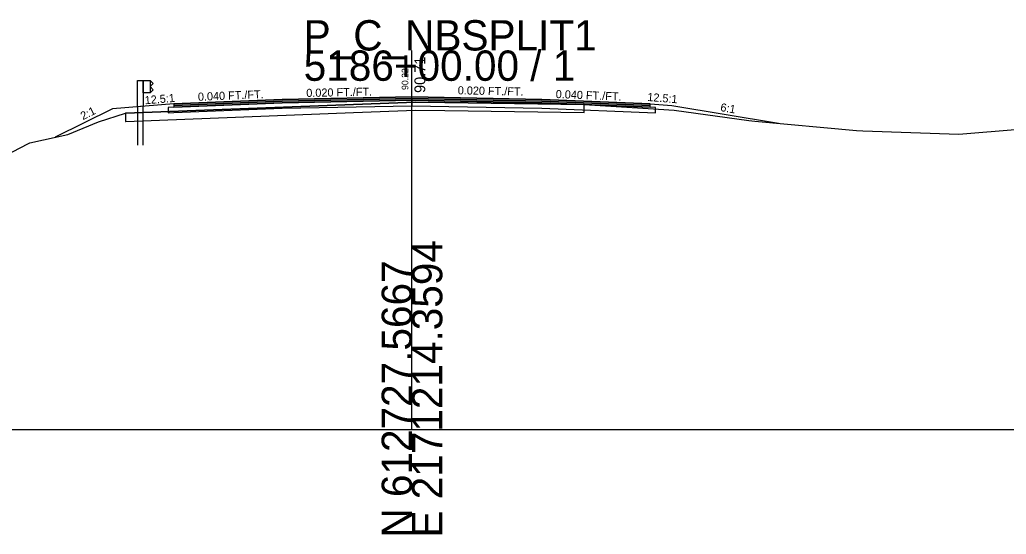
# Model space of a CAD drawing. Extents: x -26 to 1303, y -3010 to 12038.
# Drawn here: x 113.8 to 204.9, y 6490.3 to 6537.8 of the extents above; entities that cross this region are included whole.
import ezdxf

# ---------------------------------------------------------------- set-up
doc = ezdxf.new("R2010")
doc.units = 0
for name, color, linetype in [('RD_GPK_XS_Cell', 7, 'Continuous'), ('RD_PD_Final_TrvlWay', 7, 'Continuous'), ('RD_XS_Base', 7, 'Continuous'), ('RD_XS_ExGround', 7, 'Continuous'), ('RD_XS_ExPaveRet', 7, 'Continuous'), ('RD_XS_GR', 7, 'Continuous'), ('RD_XS_Greenside', 7, 'Continuous'), ('RD_XS_Pave', 7, 'Continuous'), ('RD_XS_PaveOvlay_CP', 7, 'Continuous'), ('RD_XS_TieSlope', 7, 'Continuous'), ('RD_XS_TX_Elev_EX', 7, 'Continuous'), ('RD_XS_TX_Elev_PR', 7, 'Continuous'), ('RD_XS_TX_ShdSlope', 7, 'Continuous'), ('RD_XS_TX_Slope', 7, 'Continuous')]:
    doc.layers.add(name, color=color, linetype=linetype)

msp = doc.modelspace()

# ---------------------------------------------------------------- linework, layer by layer
at = {"layer": 'RD_GPK_XS_Cell'}
for p, q in [((150, 6500), (150, 6535)), ((0, 6500), (150, 6500)), ((150, 6500), (300, 6500))]:
    msp.add_line(p, q, dxfattribs=at)
at = {"layer": 'RD_PD_Final_TrvlWay'}
for p, q in [((125.167, 6529.847), (124.667, 6529.807)), ((124.667, 6529.807), (124.667, 6526.242)), ((125.167, 6526.242), (125.167, 6529.847))]:
    msp.add_line(p, q, dxfattribs=at)
at = {"layer": 'RD_XS_Base'}
for p, q in [((138, 6530.156), (128, 6529.756)), ((150, 6530.396), (138, 6530.156)), ((138, 6530.156), (138, 6530.156)), ((150, 6530.396), (150, 6530.555)), ((150, 6530.555), (150, 6530.555)), ((150, 6530.555), (150, 6530.555)), ((150, 6530.555), (150, 6529.896)), ((150, 6529.896), (150, 6530.396)), ((150, 6530.396), (150, 6530.396)), ((150, 6530.396), (150, 6530.396)), ((150, 6530.396), (150, 6530.396)), ((162, 6530.156), (150, 6530.396)), ((172, 6529.756), (162, 6530.156)), ((164, 6530.076), (164, 6530.076)), ((128, 6529.756), (127.5, 6529.736)), ((127.5, 6529.736), (127.5, 6529.736)), ((127.5, 6529.736), (127.5, 6529.236)), ((127.5, 6529.236), (128, 6529.256)), ((128, 6529.756), (128, 6529.756)), ((128, 6529.256), (138, 6529.656)), ((128, 6529.256), (128, 6529.256)), ((138, 6529.656), (150, 6529.896)), ((138, 6529.656), (138, 6529.656)), ((150, 6529.896), (150, 6529.896)), ((150, 6529.896), (150, 6529.896)), ((150, 6529.896), (162, 6529.656)), ((162, 6529.656), (172.5, 6529.236)), ((164, 6529.576), (164, 6529.576)), ((172.5, 6529.736), (172, 6529.756)), ((172, 6529.756), (172, 6529.756)), ((172.5, 6529.236), (172.5, 6529.736)), ((172.5, 6529.736), (172.5, 6529.736))]:
    msp.add_line(p, q, dxfattribs=at)
at = {"layer": 'RD_XS_ExGround'}
msp.add_lwpolyline([(109.031, 6523.498), (114.53, 6526.391), (114.702, 6526.468), (118.219, 6527.226), (121.047, 6528.415), (123.549, 6529.203), (123.576, 6529.203), (144.6, 6530.017), (150.326, 6530.235), (153.034, 6530.199), (165.896, 6530.006), (171.816, 6529.647), (174.223, 6529.501), (181.117, 6528.535), (181.376, 6528.499), (181.652, 6528.475), (191.062, 6527.607), (191.646, 6527.583), (200.495, 6527.27), (211.256, 6528.175)], dxfattribs=at)
at = {"layer": 'RD_XS_ExPaveRet'}
for p, q in [((144.6, 6530.017), (123.576, 6529.203)), ((150.326, 6530.235), (144.6, 6530.017)), ((153.034, 6530.199), (150.326, 6530.235)), ((123.576, 6529.203), (123.549, 6529.203))]:
    msp.add_line(p, q, dxfattribs=at)
for points in [[(165.896, 6530.006), (153.034, 6530.199), (153.034, 6530.199), (150.326, 6530.235), (144.6, 6530.017), (144.6, 6530.017), (123.576, 6529.203), (123.576, 6529.203), (123.576, 6529.203), (123.549, 6529.203), (123.549, 6528.453), (123.549, 6528.453), (123.576, 6528.453), (123.576, 6528.453), (123.576, 6528.453), (144.6, 6529.267), (144.6, 6529.267), (150.326, 6529.485), (153.034, 6529.449), (153.034, 6529.449), (165.896, 6529.256), (165.896, 6529.256), (165.896, 6529.256), (165.896, 6530.006), (165.896, 6530.006)], [(123.549, 6529.203), (123.549, 6528.453), (123.576, 6528.453), (144.6, 6529.267), (150.326, 6529.485), (153.034, 6529.449), (165.896, 6529.256), (165.896, 6530.006), (153.034, 6530.199)]]:
    msp.add_lwpolyline(points, dxfattribs=at)
at = {"layer": 'RD_XS_GR'}
for points in [[(125.167, 6532.242), (125.167, 6529.847), (124.667, 6529.807), (124.667, 6532.242), (124.917, 6532.242), (125.167, 6532.242)], [(125.834, 6532.242), (125.834, 6531.075), (125.167, 6531.075), (125.167, 6532.242), (125.834, 6532.242)], [(125.834, 6532.242), (125.834, 6532.242), (125.834, 6532.242), (125.834, 6531.075), (126.105, 6531.367), (126.105, 6531.367), (125.834, 6531.659), (125.834, 6531.659), (126.105, 6531.95), (126.105, 6531.95), (125.834, 6532.242)]]:
    msp.add_lwpolyline(points, dxfattribs=at)
at = {"layer": 'RD_XS_Greenside'}
for p, q in [((122.355, 6529.622), (117.064, 6526.977)), ((174, 6529.914), (183.852, 6528.272))]:
    msp.add_line(p, q, dxfattribs=at)
at = {"layer": 'RD_XS_Pave'}
for p, q in [((138, 6530.474), (128, 6530.074)), ((138, 6530.315), (128, 6529.915)), ((128, 6529.915), (138, 6530.315)), ((128, 6529.756), (138, 6530.156)), ((128, 6530.074), (128, 6530.074)), ((128, 6530.074), (128, 6529.915)), ((150, 6530.714), (138, 6530.474)), ((150, 6530.555), (138, 6530.315)), ((138, 6530.315), (150, 6530.555)), ((138, 6530.474), (138, 6530.474)), ((138, 6530.156), (150, 6530.396)), ((138, 6530.315), (138, 6530.315)), ((138, 6530.315), (138, 6530.315)), ((138, 6530.156), (138, 6530.156)), ((162, 6530.474), (150, 6530.714)), ((150, 6530.714), (150, 6530.714)), ((150, 6530.714), (150, 6530.714)), ((150, 6530.396), (150, 6530.555)), ((150, 6530.555), (150, 6530.555)), ((150, 6530.555), (150, 6530.555)), ((150, 6530.555), (150, 6530.555)), ((150, 6530.555), (150, 6530.555)), ((150, 6530.555), (162, 6530.315)), ((162, 6530.315), (150, 6530.555)), ((150, 6530.555), (150, 6530.555)), ((150, 6530.555), (150, 6530.555)), ((150, 6530.555), (150, 6530.396)), ((150, 6530.396), (150, 6530.396)), ((150, 6530.396), (150, 6530.396)), ((150, 6530.396), (162, 6530.156)), ((172, 6530.074), (162, 6530.474)), ((162, 6530.315), (172, 6529.915)), ((172, 6529.915), (162, 6530.315)), ((162, 6530.156), (172, 6529.756)), ((164, 6530.394), (164, 6530.394)), ((164, 6530.235), (164, 6530.235)), ((164, 6530.235), (164, 6530.235)), ((164, 6530.076), (164, 6530.076)), ((172, 6529.915), (172, 6530.074)), ((172, 6530.074), (172, 6530.074)), ((128, 6529.915), (128, 6529.915)), ((128, 6529.915), (128, 6529.756)), ((172, 6529.756), (172, 6529.915)), ((172, 6529.915), (172, 6529.915))]:
    msp.add_line(p, q, dxfattribs=at)
at = {"layer": 'RD_XS_PaveOvlay_CP'}
for p, q in [((128, 6530.074), (138, 6530.474)), ((138, 6530.474), (150, 6530.714)), ((150, 6530.714), (162, 6530.474)), ((162, 6530.474), (172, 6530.074))]:
    msp.add_line(p, q, dxfattribs=at)
at = {"layer": 'RD_XS_TieSlope'}
for p, q in [((128, 6530.074), (122.355, 6529.622)), ((172, 6530.074), (174, 6529.914))]:
    msp.add_line(p, q, dxfattribs=at)

# ---------------------------------------------------------------- texts
at = {"layer": 'RD_GPK_XS_Cell'}
for s, p in [('P_C_NBSPLIT1', (140, 6535)), ('5186+00.00 / 1', (140, 6532.2))]:
    msp.add_text(s, height=2.8, dxfattribs=at).set_placement(p)
for s, p in [('E 2171214.3594', (152.8, 6490)), ('N 612727.5667', (150, 6490))]:
    msp.add_text(s, height=2.8, rotation=90, dxfattribs=at).set_placement(p)
at = {"layer": 'RD_XS_TX_Elev_EX'}
msp.add_text('90.22', height=0.6, rotation=90, dxfattribs=at).set_placement((149.656, 6531.351))
at = {"layer": 'RD_XS_TX_Elev_PR'}
msp.add_text('90.71', height=1, rotation=90, dxfattribs=at).set_placement((151.227, 6531.078))
at = {"layer": 'RD_XS_TX_ShdSlope'}
for rotation, p in [(4.57392, (125.35, 6530.029)), (355.42608, (171.711, 6530.342))]:
    msp.add_text('12.5:1', height=0.75, rotation=rotation, dxfattribs=at).set_placement(p)
at = {"layer": 'RD_XS_TX_Slope'}
for s, rotation, p in [('0.040 FT./FT.', 2.29061, (130.247, 6530.349)), ('0.020 FT./FT.', 1.14576, (140.248, 6530.704)), ('0.020 FT./FT.', 358.85424, (154.222, 6530.95)), ('0.040 FT./FT.', 357.70939, (163.262, 6530.609)), ('6:1', 350.53768, (178.44, 6529.407)), ('2:1', 26.56505, (119.619, 6528.555))]:
    msp.add_text(s, height=0.75, rotation=rotation, dxfattribs=at).set_placement(p)

doc.saveas('drawing.dxf')
